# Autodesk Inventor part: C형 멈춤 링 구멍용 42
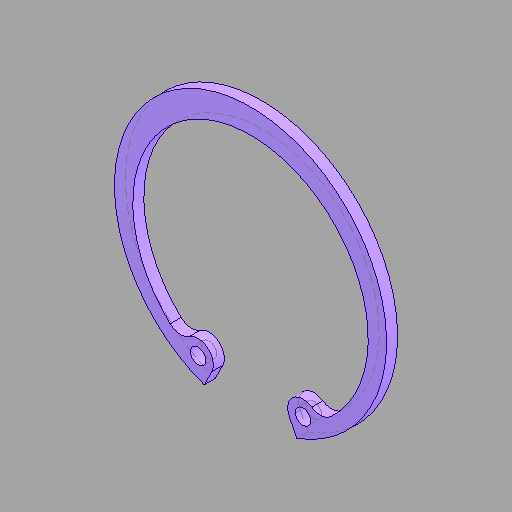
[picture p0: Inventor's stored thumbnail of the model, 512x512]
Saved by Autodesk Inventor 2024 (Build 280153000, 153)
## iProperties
Created: 2025-11
Part Number: C형 멈춤 링 구멍용 42
Material: 강철, 연강
Description: 리테이닝 링(C형)
Document SubType Name: Modeling
Designer: Edu09
Density: 7.85 g/cm^3
Appearance: 기본값
Author: jhkim
Sending System: Autodesk Inventor 2026
Preprocessor: ST-DEVELOPER v20.1
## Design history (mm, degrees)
feature "Solid1"
node "솔리드1"
